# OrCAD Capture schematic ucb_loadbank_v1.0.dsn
size C; title: UCB_LoadBank; rev: 1.4; company: University of Arkansas (NCREPT); note: 700 W. Research Center Blvd; note: Fayetteville, AR 72701
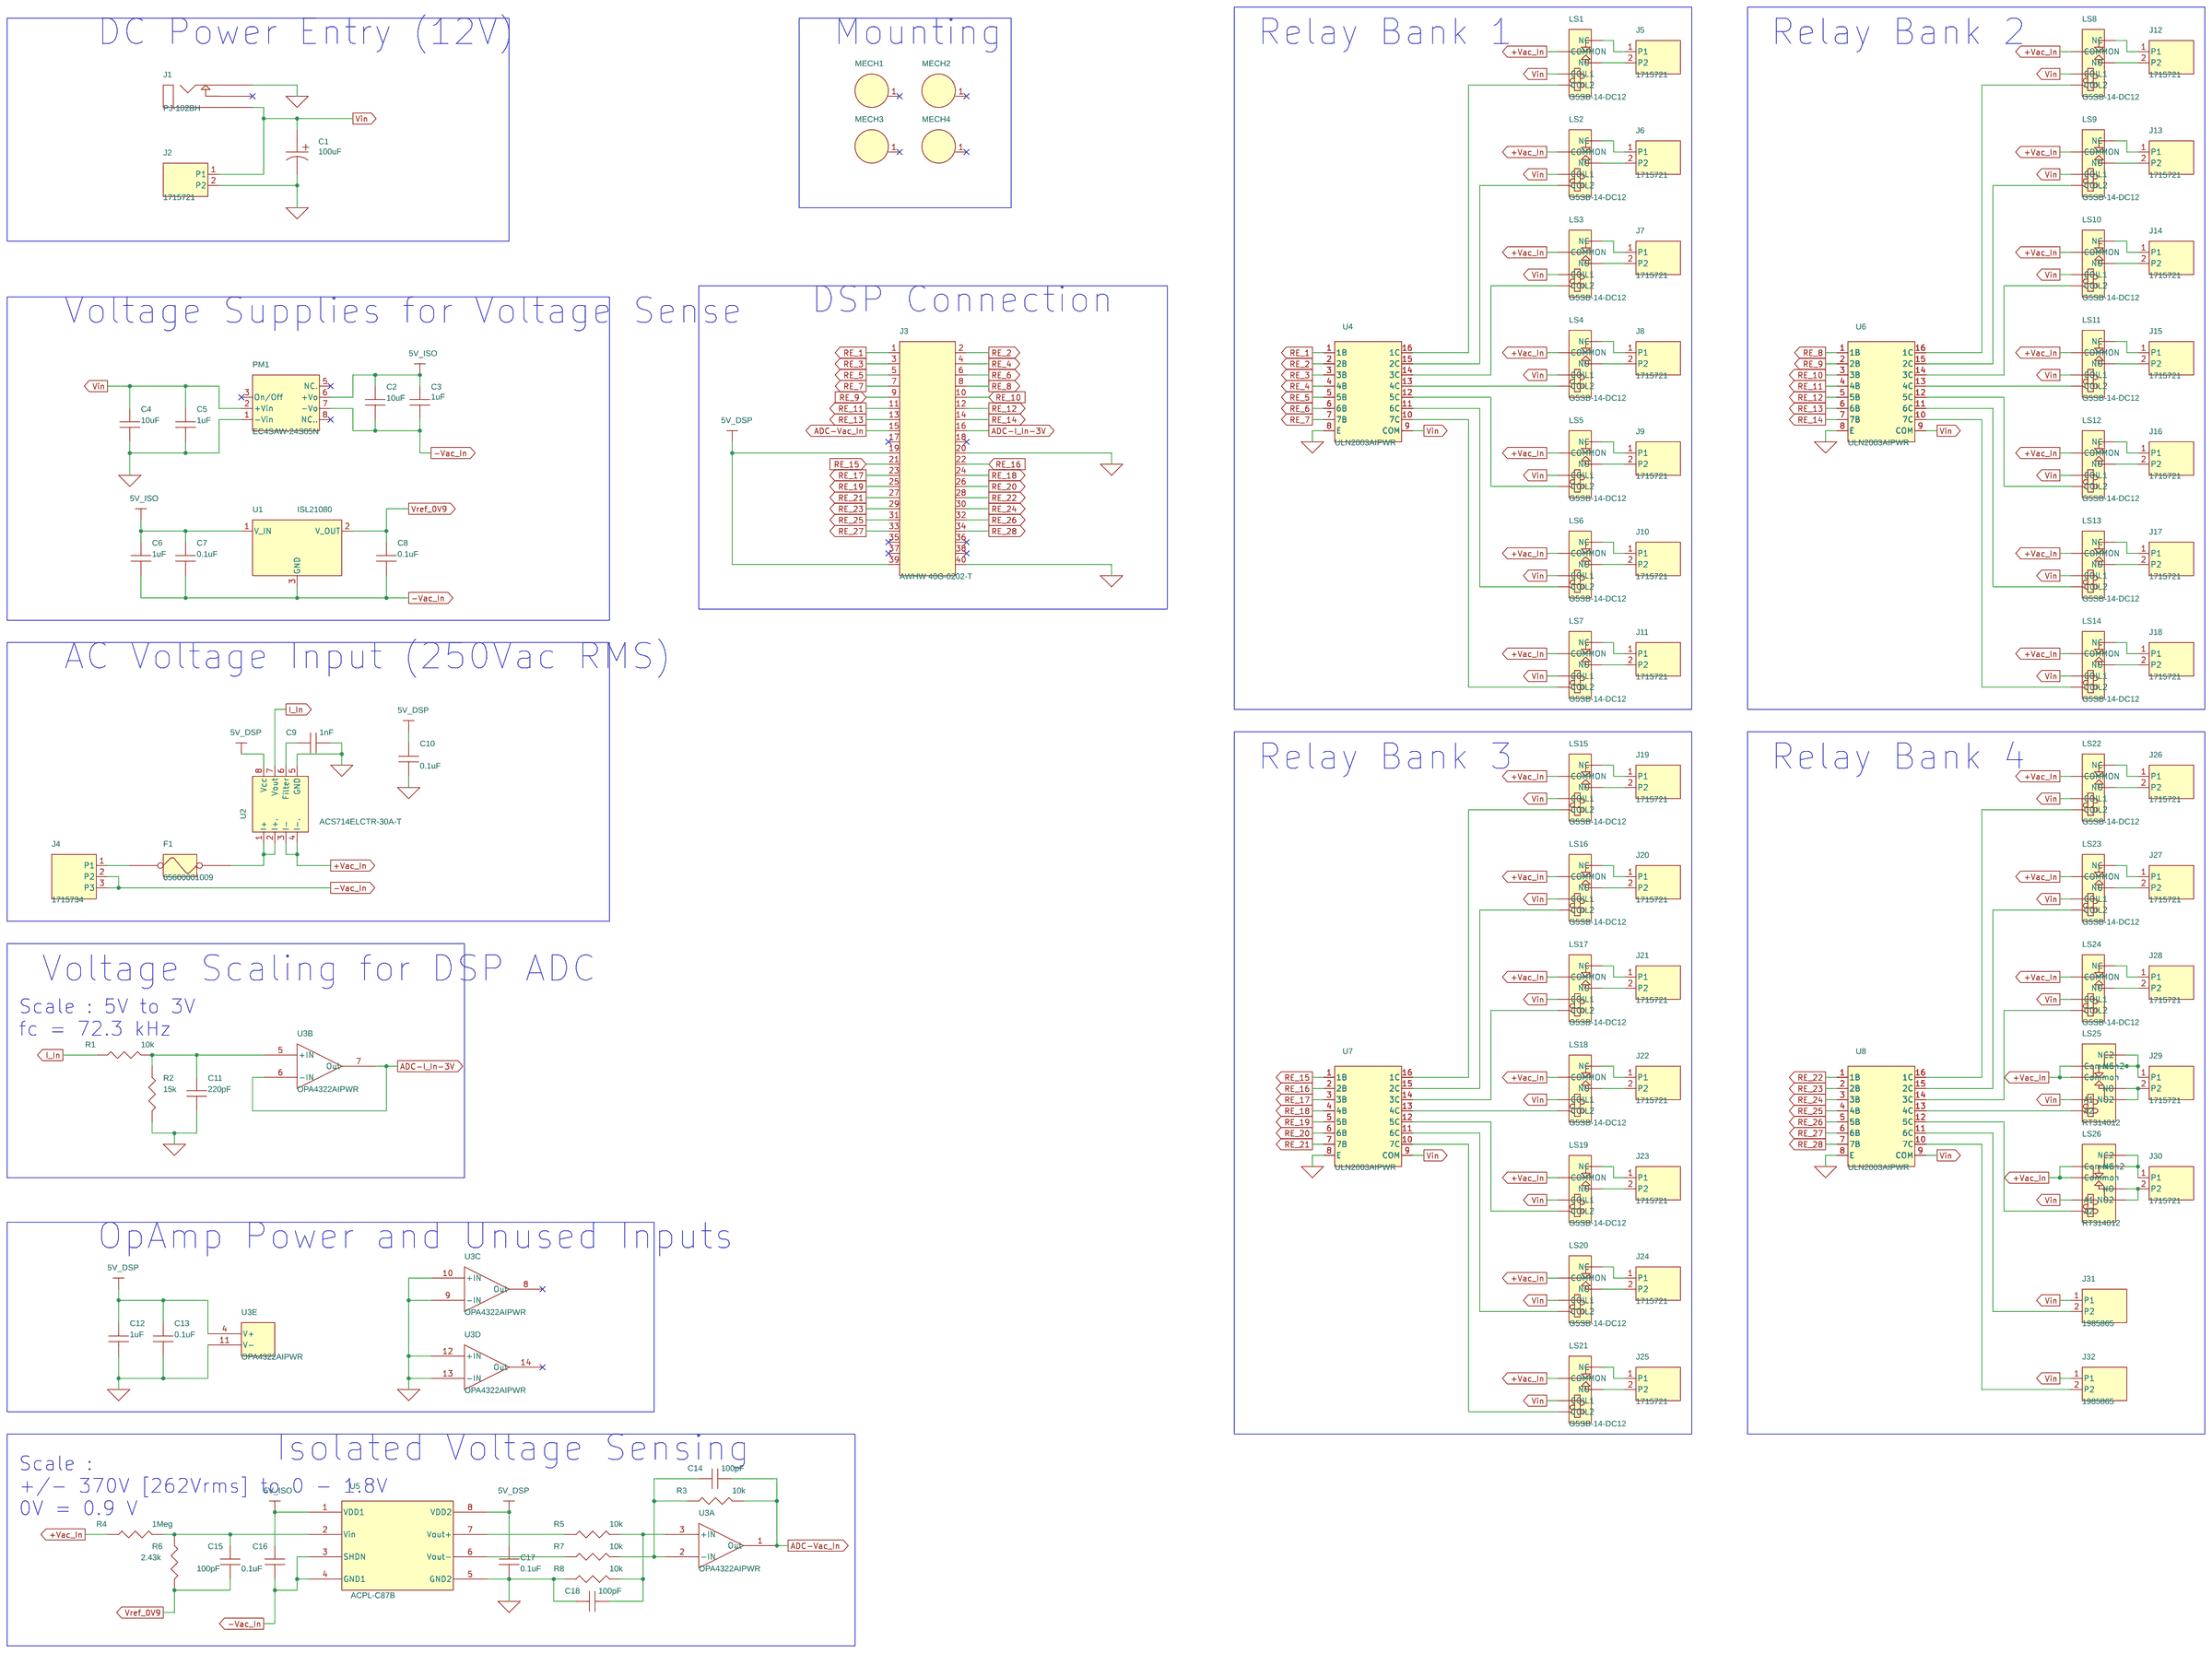
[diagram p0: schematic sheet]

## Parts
C1  100uF  [UVZ1H101MPD]
C2  10uF  [C_1206]
C3  1uF  [C_0603]
C4  10uF  [C_1206]
C5  1uF  [C_0603]
C6  1uF  [C_0603]
C7  0.1uF  [C_0603]
C8  0.1uF  [C_0603]
C9  1nF  [C_0603]
C10  0.1uF  [C_0603]
C11  220pF  [C_0603]
C12  1uF  [C_0603]
C13  0.1uF  [C_0603]
C14  100pF  [C_0603]
C15  100pF  [C_0603]
C16  0.1uF  [C_0603]
C17  0.1uF  [C_0603]
C18  100pF  [C_0603]
F1  65600001009  [FUSE_5X20MM]
J1  PJ-102BH  [DC-PWR_JACK]
J2  1715721  [1715721]
J3  AWHW 40G-0202-T  [40-IDC-M]
J4  1715734  [1715734]
J5  1715721  [1715721]
J6  1715721  [1715721]
J7  1715721  [1715721]
J8  1715721  [1715721]
J9  1715721  [1715721]
J10  1715721  [1715721]
J11  1715721  [1715721]
J12  1715721  [1715721]
J13  1715721  [1715721]
J14  1715721  [1715721]
J15  1715721  [1715721]
J16  1715721  [1715721]
J17  1715721  [1715721]
J18  1715721  [1715721]
J19  1715721  [1715721]
J20  1715721  [1715721]
J21  1715721  [1715721]
J22  1715721  [1715721]
J23  1715721  [1715721]
J24  1715721  [1715721]
J25  1715721  [1715721]
J26  1715721  [1715721]
J27  1715721  [1715721]
J28  1715721  [1715721]
J29  1715721  [1715721]
J30  1715721  [1715721]
J31  1985865  [1985865]
J32  1985865  [1985865]
LS1  G5SB-14-DC12  [G5SB]
LS2  G5SB-14-DC12  [G5SB]
LS3  G5SB-14-DC12  [G5SB]
LS4  G5SB-14-DC12  [G5SB]
LS5  G5SB-14-DC12  [G5SB]
LS6  G5SB-14-DC12  [G5SB]
LS7  G5SB-14-DC12  [G5SB]
LS8  G5SB-14-DC12  [G5SB]
LS9  G5SB-14-DC12  [G5SB]
LS10  G5SB-14-DC12  [G5SB]
LS11  G5SB-14-DC12  [G5SB]
LS12  G5SB-14-DC12  [G5SB]
LS13  G5SB-14-DC12  [G5SB]
LS14  G5SB-14-DC12  [G5SB]
LS15  G5SB-14-DC12  [G5SB]
LS16  G5SB-14-DC12  [G5SB]
LS17  G5SB-14-DC12  [G5SB]
LS18  G5SB-14-DC12  [G5SB]
LS19  G5SB-14-DC12  [G5SB]
LS20  G5SB-14-DC12  [G5SB]
LS21  G5SB-14-DC12  [G5SB]
LS22  G5SB-14-DC12  [G5SB]
LS23  G5SB-14-DC12  [G5SB]
LS24  G5SB-14-DC12  [G5SB]
LS25  RT314012  [TE_RT1-FORMC_5MM]
LS26  RT314012  [TE_RT1-FORMC_5MM]
MECH1  Mech_Hole  [4-40_SCREW]
MECH2  Mech_Hole  [4-40_SCREW]
MECH3  Mech_Hole  [4-40_SCREW]
MECH4  Mech_Hole  [4-40_SCREW]
PM1  EC4SAW-24S05N  [SIP-8]
R1  10k  [R_0603]
R2  15k  [R_0603]
R3  10k  [R_0603]
R4  1Meg  [R_0603]
R5  10k  [R_0603]
R6  2.43k  [R_0603]
R7  10k  [R_0603]
R8  10k  [R_0603]
U1  ISL21080  [SOT_23-3]
U2  ACS714ELCTR-30A-T  [8-SOIC]
U3  OPA4322AIPWR  [OPA4332_14-TSSOP]  (sections A,B,C,D,E)
U4  ULN2003AIPWR  [16-TSSOP]
U5  ACPL-C87B  [ACPL-C87X]
U6  ULN2003AIPWR  [16-TSSOP]
U7  ULN2003AIPWR  [16-TSSOP]
U8  ULN2003AIPWR  [16-TSSOP]

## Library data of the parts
C1 = CAP_P: Electrolytic Capacitor (50V/100uF); Manufacturer: Nichicon; Part_Number: Cap-00020; Voltage: 50V; Datasheet: Nicicon-e-uvz-880014.pdf
C2 C4 = CAP_NP: 10µF ±20% 35V X7R MLCC; Manufacturer: TDK; Manufacturer_Part_Number: C3216X7R1V106M160AC; Part_Number: Cap-00002; Tolerance: 20%; Voltage: 35V; Datasheet: TDK-mlcc_commercial_general_en.pdf
C3 C5 C6 C12 = CAP_NP: 1µF ±10% 35V X7R MLCC; Manufacturer: TDK; Manufacturer_Part_Number: C1608X7R1V105K080AC; Part_Number: Cap-00008; Tolerance: 10%; Voltage: 35V; Datasheet: TDK-mlcc_commercial_general_en.pdf
C7 C8 C10 C13 C16 C17 = CAP_NP: 0.1µF ±10% 50V X7R MLCC; Manufacturer: TDK; Manufacturer_Part_Number: C1608X7R1H104K080AA; Part_Number: Cap-00001; Tolerance: 10%; Voltage: 50V; Datasheet: TDK-mlcc_commercial_general_en.pdf
C9 = CAP_NP: 1nF ±10% 100V X7R MLCC; Manufacturer: TDK; Manufacturer_Part_Number: C1608X7R2A102K080AA; Part_Number: Cap-00005; Tolerance: 10%; Voltage: 100V; Datasheet: TDK-mlcc_commercial_general_en.pdf
C11 = CAP_NP: 0.22nF ±5% 100V C0G MLCC; Manufacturer: TDK; Manufacturer_Part_Number: C1608C0G2A221J080AA; Part_Number: Cap-00018; Tolerance: 5%; Voltage: 100V; Datasheet: TDK-mlcc_commercial_general_en.pdf
C14 C15 C18 = CAP_NP: 100pF ±10% 100V C0G MLCC; Manufacturer: TDK; Manufacturer_Part_Number: C1608C0G2A101K080AA; Part_Number: Cap-00013; Tolerance: 10%; Voltage: 100V; Datasheet: TDK-mlcc_commercial_general_en.pdf
F1 = FUSEHOLDER: Fuse Holder, 5x20mm, TH; Manufacturer: Littelfuse; Part_Number: F-00001; Datasheet: Littelfuse-656_659_660_LF_060102-16982.pdf
J1 = DC-Jack_3: DC Power Jack, 2.5mm Center Pin, TH; Manufacturer: CUI; Part_Number: Con-00017; STEP_Model: pj-102bh.stp; Datasheet: CUI-PJ-102BH-524153.pdf
J2 J5-J30 = Connector-2: PCB Terminal Block, 2-position, 90 degrees, 5.08mm; Manufacturer: Phoenix Contact; Part_Number: Con-00006; Rating: 17.5A; STEP_Model: 1715721.stp; Voltage: 400V; Datasheet: PhoenixContact-1715734.pdf
J3 = Header_2x20: 40-POS Header, Shrouded, 0.100", TH; Manufacturer: Assmann; Part_Number: Con-00015; STEP_Model: HDB-40.stp; User_Field1: SBH11-PBPC-D20-ST-BK; Datasheet: Assmann-AWHW-xxG-0x02-T.pdf
J4 = Connector-3: PCB Terminal Block, 3-position, 90 degrees, 5.08mm; Manufacturer: Phoenix Contact; Part_Number: Con-00007; Rating: 17.5A; STEP_Model: 1715734.stp; Voltage: 400V; Datasheet: PhoenixContact-1715734.pdf
J31 J32 = Connector-2: PCB Terminal Block, 2-position, 90 degrees, 5.08mm, 10mm-Tall; Manufacturer: Phoenix Contact; Part_Number: TMP-228; Rating: 13.5A; STEP_Model: 1985865_03.stp; Voltage: 320V; Datasheet: PhoenixContact-1985865-927167.pdf
LS1-LS24 = RELAY_SPDT: Part_Number: K-00001
LS25 LS26 = RELAY-SPDT_TE-RT1_16A: Part_Number: TMP-242
MECH1-MECH4 = Mech_Hole: Mounting Hole for 4-40 Screw, 0.125"; Part_Number: Con-00005
PM1 = EC4SA: Isolated DC/DC Converters 6 Watt, 9-36 Vin, 5 Vout; Manufacturer: Cincon; Part_Number: PS-00002; STEP_Model: PwrMod-SIP8.stp; Datasheet: CINCON-EC4SAW V10-557886.pdf
R1 R3 R5 R7 R8 = R-Standard: 10k Ohm, 1%, 0603; Manufacturer: KOA Speer; Manufacturer_Part_Number: RK73H1JTTD1002F; Part_Number: Res-00031; Rating: 0.1W; Tolerance: 1%; Datasheet: KOA-RK73H-5715.pdf
R2 = R-Standard: 15k Ohm, 1%, 0603; Manufacturer: KOA Speer; Manufacturer_Part_Number: RK73H1JTTD1502F; Part_Number: Res-00037; Rating: 0.1W; Tolerance: 1%; Datasheet: KOA-RK73H-5715.pdf
R4 = R-Standard: 1M Ohm, 1%, 0603; Manufacturer: KOA Speer; Manufacturer_Part_Number: RK73H1JTTD1004F; Part_Number: Res-00035; Rating: 0.1W; Tolerance: 1%; Datasheet: KOA-RK73H-5715.pdf
R6 = R-Standard: 2.43k Ohm, 1%, 0603; Manufacturer: KOA Speer; Manufacturer_Part_Number: RK73H1JTTD2431F; Part_Number: Res-00038; Rating: 0.1W; Tolerance: 1%; Datasheet: KOA-RK73H-5715.pdf
U1 = ISL21080: 0.9V Voltage Reference, ±0.7%; Manufacturer: Intersil; Manufacturer_Part_Number: ISL21080DIH309Z-TK; Part_Number: IC-00014; STEP_Model: SOT23-3.stp; Datasheet: Intersil-isl21080.pdf
U2 = ACS714: Hall Effect Sensor, 30A AC/DC, 66mV/A; Manufacturer: Allegro; Part_Number: IC-00003; Tolerance: 1.50%; Datasheet: Allegro-ACS714-Datasheet.pdf
U3 = OPA4322AIPWR: Quad OpAmp, 20 MHz; Manufacturer: TI; Part_Number: IC-00012; STEP_Model: TSSOP14.stp; User_Field1: https://www.google.com/; Datasheet: TI-opa4322.pdf
U4 U6-U8 = ULN2003AI: High-Voltage, High-Current Darlington Transistor Array; Manufacturer: TI; Part_Number: IC-00015; STEP_Model: TSSOP65P640X120-16N.stp; Datasheet: TI-uln2003ai-450862.pdf
U5 = ACPL-C87B: Isolation OpAmp, 100 kHz; Manufacturer: Avago; Manufacturer_Part_Number: ACPL-C87B-000E; Part_Number: IC-00011; STEP_Model: SOIC08 wide.stp; Datasheet: Avago-AV02-3563EN_DS_ACPL-C87x_04Mar2013.pdf

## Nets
5V_DSP: C10.1 C12.1 C13.1 C17.1 J3.19 J3.39 U2.8(Vcc) U3.4(V+) U5.8(VDD2)
5V_Iso: C2.1 C3.1 C6.1 C7.1 C16.1 PM1.6(+Vo) U1.1(V_IN) U5.1(VDD1)
GND_SIGNAL: C1.2 C4.2 C5.2 C9.2 C10.2 C11.2 C12.2 C13.2 C17.2 C18.1 J1.2 J2.2(P2) J3.20 J3.40 PM1.1(-Vin) R2.2 R8.1 U2.5(GND) U3.9(-IN) U3.10(+IN) U3.11(V-) U3.12(+IN) U3.13(-IN) U4.8(E) U5.5(GND2) U6.8(E) U7.8(E) U8.8(E)
Vin: C1.1 C4.1 C5.1 J1.1 J2.1(P1) J31.1(P1) J32.1(P1) LS1.1(COIL1) LS2.1(COIL1) LS3.1(COIL1) LS4.1(COIL1) LS5.1(COIL1) LS6.1(COIL1) LS7.1(COIL1) LS8.1(COIL1) LS9.1(COIL1) LS10.1(COIL1) LS11.1(COIL1) LS12.1(COIL1) LS13.1(COIL1) LS14.1(COIL1) LS15.1(COIL1) LS16.1(COIL1) LS17.1(COIL1) LS18.1(COIL1) LS19.1(COIL1) LS20.1(COIL1) LS21.1(COIL1) LS22.1(COIL1) LS23.1(COIL1) LS24.1(COIL1) LS25.1(A1) LS26.1(A1) PM1.2(+Vin) U4.9(COM) U6.9(COM) U7.9(COM) U8.9(COM)
+Vac_In: LS1.2(COMMON) LS2.2(COMMON) LS3.2(COMMON) LS4.2(COMMON) LS5.2(COMMON) LS6.2(COMMON) LS7.2(COMMON) LS8.2(COMMON) LS9.2(COMMON) LS10.2(COMMON) LS11.2(COMMON) LS12.2(COMMON) LS13.2(COMMON) LS14.2(COMMON) LS15.2(COMMON) LS16.2(COMMON) LS17.2(COMMON) LS18.2(COMMON) LS19.2(COMMON) LS20.2(COMMON) LS21.2(COMMON) LS22.2(COMMON) LS23.2(COMMON) LS24.2(COMMON) LS25.5(Common) LS25.6(Common2) LS26.5(Common) LS26.6(Common2) R4.1 U2.3(I-) U2.4(I-.)
-Vac_In: C2.2 C3.2 C6.2 C7.2 C8.2 C16.2 J4.2(P2) J4.3(P3) PM1.7(-Vo) U1.3(GND) U5.3(SHDN) U5.4(GND1)
ADC-I_In-3V: J3.16 U3.6(-IN) U3.7(Out)
ADC-Vac_In: C14.2 J3.15 R3.2 U3.1(Out)
I_In: R1.1 U2.7(Vout)
RE_1: J3.1 U4.1(1B)
RE_2: J3.2 U4.2(2B)
RE_3: J3.3 U4.3(3B)
RE_4: J3.4 U4.4(4B)
RE_5: J3.5 U4.5(5B)
RE_6: J3.6 U4.6(6B)
RE_7: J3.7 U4.7(7B)
RE_8: J3.8 U6.1(1B)
RE_9: J3.9 U6.2(2B)
RE_10: J3.10 U6.3(3B)
RE_11: J3.11 U6.4(4B)
RE_12: J3.12 U6.5(5B)
RE_13: J3.13 U6.6(6B)
RE_14: J3.14 U6.7(7B)
RE_15: J3.21 U7.1(1B)
RE_16: J3.22 U7.2(2B)
RE_17: J3.23 U7.3(3B)
RE_18: J3.24 U7.4(4B)
RE_19: J3.25 U7.5(5B)
RE_20: J3.26 U7.6(6B)
RE_21: J3.27 U7.7(7B)
RE_22: J3.28 U8.1(1B)
RE_23: J3.29 U8.2(2B)
RE_24: J3.30 U8.3(3B)
RE_25: J3.31 U8.4(4B)
RE_26: J3.32 U8.5(5B)
RE_27: J3.33 U8.6(6B)
RE_28: J3.34 U8.7(7B)
Vref_0V9: C8.1 C15.2 R6.2 U1.2(V_OUT)
N38694: F1.2 U2.1(I+) U2.2(I+.)
N41110: C9.1 U2.6(Filter)
N283390: C11.1 R1.2 R2.1 U3.5(+IN)
N283722: C18.2 R5.2 R8.2 U3.3(+IN)
N283726: R5.1 U5.7(Vout+)
N283730: R7.1 U5.6(Vout-)
N283734: C14.1 R3.1 R7.2 U3.2(-IN)
N283872: C15.1 R4.2 R6.1 U5.2(Vin)
N301218: LS7.5(COIL2) U4.10(7C)
N301328: LS6.5(COIL2) U4.11(6C)
N301340: LS5.5(COIL2) U4.12(5C)
N301511: LS4.5(COIL2) U4.13(4C)
N301526: LS3.5(COIL2) U4.14(3C)
N301538: LS2.5(COIL2) U4.15(2C)
N301550: LS1.5(COIL2) U4.16(1C)
N303080: J5.1(P1) LS1.4(NC)
N303092: J5.2(P2) LS1.3(NO)
N303096: J6.2(P2) LS2.3(NO)
N303100: J6.1(P1) LS2.4(NC)
N303115: J7.2(P2) LS3.3(NO)
N303119: J7.1(P1) LS3.4(NC)
N303134: J8.2(P2) LS4.3(NO)
N303138: J8.1(P1) LS4.4(NC)
N303150: J9.2(P2) LS5.3(NO)
N303154: J9.1(P1) LS5.4(NC)
N303169: J10.2(P2) LS6.3(NO)
N303173: J10.1(P1) LS6.4(NC)
N303185: J11.2(P2) LS7.3(NO)
N303189: J11.1(P1) LS7.4(NC)
N307291: F1.1 J4.1(P1)
N308898: LS14.5(COIL2) U6.10(7C)
N308922: LS13.5(COIL2) U6.11(6C)
N308934: LS12.5(COIL2) U6.12(5C)
N308946: LS11.5(COIL2) U6.13(4C)
N308950: LS10.5(COIL2) U6.14(3C)
N308962: LS9.5(COIL2) U6.15(2C)
N308974: LS8.5(COIL2) U6.16(1C)
N309142: J12.1(P1) LS8.4(NC)
N309154: J12.2(P2) LS8.3(NO)
N309158: J13.2(P2) LS9.3(NO)
N309162: J13.1(P1) LS9.4(NC)
N309174: J14.2(P2) LS10.3(NO)
N309178: J14.1(P1) LS10.4(NC)
N309190: J15.2(P2) LS11.3(NO)
N309194: J15.1(P1) LS11.4(NC)
N309206: J16.2(P2) LS12.3(NO)
N309210: J16.1(P1) LS12.4(NC)
N309222: J17.2(P2) LS13.3(NO)
N309226: J17.1(P1) LS13.4(NC)
N309238: J18.2(P2) LS14.3(NO)
N309242: J18.1(P1) LS14.4(NC)
N310612: LS21.5(COIL2) U7.10(7C)
N310636: LS20.5(COIL2) U7.11(6C)
N310648: LS19.5(COIL2) U7.12(5C)
N310660: LS18.5(COIL2) U7.13(4C)
N310664: LS17.5(COIL2) U7.14(3C)
N310676: LS16.5(COIL2) U7.15(2C)
N310688: LS15.5(COIL2) U7.16(1C)
N310856: J19.1(P1) LS15.4(NC)
N310868: J19.2(P2) LS15.3(NO)
N310872: J20.2(P2) LS16.3(NO)
N310876: J20.1(P1) LS16.4(NC)
N310888: J21.2(P2) LS17.3(NO)
N310892: J21.1(P1) LS17.4(NC)
N310904: J22.2(P2) LS18.3(NO)
N310908: J22.1(P1) LS18.4(NC)
N310920: J23.2(P2) LS19.3(NO)
N310924: J23.1(P1) LS19.4(NC)
N310936: J24.2(P2) LS20.3(NO)
N310940: J24.1(P1) LS20.4(NC)
N310952: J25.2(P2) LS21.3(NO)
N310956: J25.1(P1) LS21.4(NC)
N312350: J32.2(P2) U8.10(7C)
N312374: J31.2(P2) U8.11(6C)
N312390: LS26.2(A2) U8.12(5C)
N312398: LS25.2(A2) U8.13(4C)
N312402: LS24.5(COIL2) U8.14(3C)
N312414: LS23.5(COIL2) U8.15(2C)
N312426: LS22.5(COIL2) U8.16(1C)
N312594: J26.1(P1) LS22.4(NC)
N312606: J26.2(P2) LS22.3(NO)
N312610: J27.2(P2) LS23.3(NO)
N312614: J27.1(P1) LS23.4(NC)
N312626: J28.2(P2) LS24.3(NO)
N312630: J28.1(P1) LS24.4(NC)
N312646: J29.1(P1) LS25.3(NC) LS25.4(NC2)
N314100: J30.2(P2) LS26.7(NO) LS26.8(NO2)
N314280: J29.2(P2) LS25.7(NO) LS25.8(NO2)
N314578: J30.1(P1) LS26.3(NC) LS26.4(NC2)

Not connected (* = marked no-connect by the designer): J1 3*; J3 17* 18* 35* 36* 37* 38*; MECH1 1*; MECH2 1*; MECH3 1*; MECH4 1*; PM1 3(On/Off)* 5(NC.)* 8(NC..)*; U3 8(Out)* 14(Out)*

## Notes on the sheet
- DC Power Entry (12V)
- Mounting
- Relay Bank 1
- Relay Bank 2
- DSP Connection
- Voltage Supplies for Voltage Sense
- AC Voltage Input (250Vac RMS)
- Relay Bank 3
- Relay Bank 4
- Voltage Scaling for DSP ADC
- Scale : 5V to 3V
  fc = 72.3 kHz
- OpAmp Power and Unused Inputs
- Isolated Voltage Sensing
- Scale :
  +/- 370V [262Vrms] to 0 - 1.8V
  0V = 0.9 V
